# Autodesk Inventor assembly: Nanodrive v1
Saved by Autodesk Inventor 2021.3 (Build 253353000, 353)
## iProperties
Created: 2022-07
Part Number: Nanodrive v1
Document SubType Name: Assembly
Designer: Administrator
Title: Nanodrive v1
Author: Administrator
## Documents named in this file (3)
- c:\worker\convert-fusion-r04\tmp\job-1\186\output\files\05ef811f-4573-476e-8ba5-de3f58aa0f0a\Nanodrive v1.iam
- c:\worker\convert-fusion-r04\tmp\job-1\186\output\files\05ef811f-4573-476e-8ba5-de3f58aa0f0a\Probe.ipt
- c:\worker\convert-fusion-r04\tmp\job-1\186\output\files\05ef811f-4573-476e-8ba5-de3f58aa0f0a\Part10.ipt
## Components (2 placed, 2 different names)
1. Probe:1
2. Part10
